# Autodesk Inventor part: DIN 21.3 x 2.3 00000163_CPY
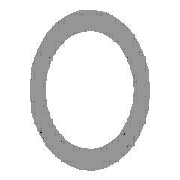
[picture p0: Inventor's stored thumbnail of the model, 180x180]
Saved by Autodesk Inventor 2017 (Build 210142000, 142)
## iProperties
Created: 2017-11
Part Number: DIN 21.3 x 2.3 00000163_CPY
Material: Steel, Mild
Description: Pipe
Document SubType Name: Modeling
Standard: DIN
Designer: iusti
Standard Revision: 2006-07
Standards Organization: DIN
Language: en-US
Size Designation: 21.3 x 2.3
Categories: <MemberInstance><Categories><Category DisplayName="Structural Shapes" InternalName="089c4875-fa83-4c05-b084-43b9cc11f5ed" Mnemonic="GRDR"><CategoryParameter Dis
Stock Number: 21.3 x 2.3
Density: 7.85 g/cm^3
Appearance: Semi-Polished
IsCustomPart: 1
G_L: 500.000 mm
G_W: 21.300 mm
G_H: 21.300 mm
_CCFamilyMember: 1
_CCFamilyDisplayName: DIN EN 10210-2 - Pipe
_FrameMemberDoc: Frame Member File
_Version: 15.0.0
_GetPNFromCC: 1
Author: iusti
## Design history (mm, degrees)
node "Start plane"
node "End plane"
sketch "Sketch"
  geometry: C1 r 8.35 at (0, 0); C2 r 10.65 at (0, 0); 2 further points
  constraints: 3 coincident, 2 centre point
  dimensions: "d0" = 21.3 diameter of C2 (= G_H); "d1" = 2.3 radial gap between concentric circles of C2 C1 (= G_T)
extrude "Body" new body sketch "Sketch" stored distance "d2" = 500 (= G_L); taper "d3" = 0 deg
node "Driven Length"
  sketch "Sketch3"
    geometry: L1 (0, 0)-(10, 0) reference
    constraints: 2 end point, 1 horizontal
  workplane "Work Plane3"
  sketch "Sketch4"
    geometry: L1 (-2, 0)-(12, 0) reference; L2 (-2, 500)-(12, 500) reference
    dimensions: "d7" = 500 distance between parallel lines of L1 L2 (derived)
body "Solid1"
other parameters: "G_H" = 21.3 [user parameter; used in 1 equation term], "G_T" = 2.3 [user parameter; used in 1 equation term], "G_L" = 500 (= d7) [user parameter; used in 1 equation term], "G_OFFSET_START" = 0 [user parameter; used in 1 equation term], "G_OFFSET_END" = 0 [user parameter; used in 1 equation term], "d4" = 0 (computed from G_OFFSET_START), "d6" = 90 deg
